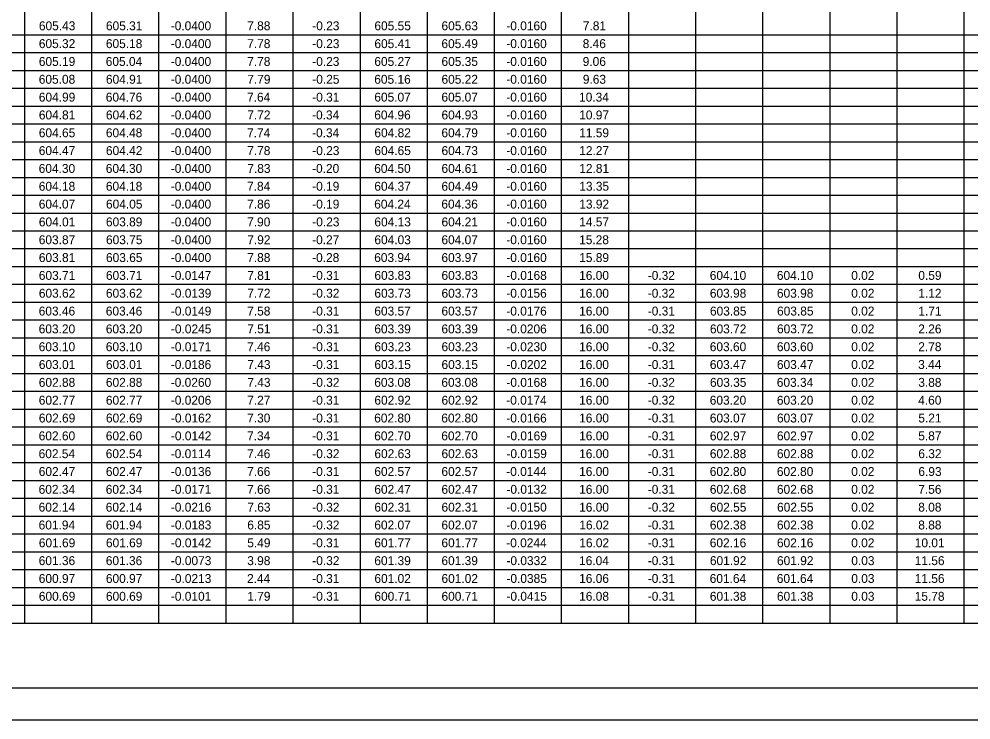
# Model space of a CAD drawing. Extents: x 0 to 34, y 0 to 22.
# Drawn here: x 7.6 to 22.56, y 0 to 11.01 of the extents above; entities that cross this region are included whole.
import ezdxf

# ---------------------------------------------------------------- set-up
doc = ezdxf.new("R2010")
doc.units = 0
for name, color, linetype in [('Default', 7, 'Continuous'), ('SH_Border', 7, 'Continuous'), ('SH_Cut_Line', 7, 'Continuous')]:
    doc.layers.add(name, color=color, linetype=linetype)

msp = doc.modelspace()

# ---------------------------------------------------------------- linework, layer by layer
at = {"layer": 'Default'}
for p, q in [((17.176, 19.376), (17.176, 1.522)), ((22.447, 19.376), (22.447, 1.522)), ((11.906, 18.833), (11.906, 1.522)), ((7.689, 18.52), (7.689, 1.522)), ((8.743, 18.52), (8.743, 1.522)), ((9.797, 18.52), (9.797, 1.522)), ((10.851, 18.52), (10.851, 1.522)), ((12.96, 18.52), (12.96, 1.522)), ((14.014, 18.52), (14.014, 1.522)), ((15.068, 18.52), (15.068, 1.522)), ((16.122, 18.52), (16.122, 1.522)), ((18.23, 18.52), (18.23, 1.522)), ((19.284, 18.52), (19.284, 1.522)), ((20.339, 18.52), (20.339, 1.522)), ((21.393, 18.52), (21.393, 1.522)), ((6.635, 10.762), (26.861, 10.762)), ((6.635, 10.482), (26.861, 10.482)), ((6.635, 10.202), (26.861, 10.202)), ((6.635, 9.922), (26.861, 9.922)), ((6.635, 9.642), (26.861, 9.642)), ((6.635, 9.362), (26.861, 9.362)), ((6.635, 9.082), (26.861, 9.082)), ((6.635, 8.802), (26.861, 8.802)), ((6.635, 8.522), (26.861, 8.522)), ((6.635, 8.242), (26.861, 8.242)), ((6.635, 7.962), (26.861, 7.962)), ((6.635, 7.682), (26.861, 7.682)), ((6.635, 7.402), (26.861, 7.402)), ((6.635, 7.122), (26.861, 7.122)), ((6.635, 6.842), (26.861, 6.842)), ((6.635, 6.562), (26.861, 6.562)), ((6.635, 6.282), (26.861, 6.282)), ((6.635, 6.002), (26.861, 6.002)), ((6.635, 5.722), (26.861, 5.722)), ((6.635, 5.442), (26.861, 5.442)), ((6.635, 5.162), (26.861, 5.162)), ((6.635, 4.882), (26.861, 4.882)), ((6.635, 4.602), (26.861, 4.602)), ((6.635, 4.322), (26.861, 4.322)), ((6.635, 4.042), (26.861, 4.042)), ((6.635, 3.762), (26.861, 3.762)), ((6.635, 3.482), (26.861, 3.482)), ((6.635, 3.202), (26.861, 3.202)), ((6.635, 2.922), (26.861, 2.922)), ((6.635, 2.642), (26.861, 2.642)), ((6.635, 2.362), (26.861, 2.362)), ((6.635, 2.082), (26.861, 2.082)), ((6.635, 1.802), (26.861, 1.802)), ((6.635, 1.522), (26.861, 1.522))]:
    msp.add_line(p, q, dxfattribs=at)
at = {"layer": 'SH_Border'}
msp.add_lwpolyline([(1.5, 21.5), (33.5, 21.5), (33.5, 0.5), (1.5, 0.5)], close=True, dxfattribs=at)
at = {"layer": 'SH_Cut_Line'}
msp.add_lwpolyline([(0, 0), (34, 0), (34, 22), (0, 22)], close=True, dxfattribs=at)

# ---------------------------------------------------------------- texts
at = {"layer": 'Default'}
for s, p in [('605.43', (7.916, 10.832)), ('605.31', (8.969, 10.832)), ('-0.0400', (9.987, 10.832)), ('7.88', (11.188, 10.832)), ('-0.23', (12.21, 10.832)), ('605.55', (13.186, 10.832)), ('605.63', (14.24, 10.832)), ('-0.0160', (15.258, 10.832)), ('7.81', (16.46, 10.832)), ('605.32', (7.915, 10.552)), ('605.18', (8.968, 10.552)), ('-0.0400', (9.987, 10.552)), ('7.78', (11.188, 10.552)), ('-0.23', (12.21, 10.552)), ('605.41', (13.186, 10.552)), ('605.49', (14.239, 10.552)), ('-0.0160', (15.258, 10.552)), ('8.46', (16.458, 10.552)), ('605.19', (7.915, 10.272)), ('605.04', (8.966, 10.272)), ('-0.0400', (9.987, 10.272)), ('7.78', (11.188, 10.272)), ('-0.23', (12.21, 10.272)), ('605.27', (13.185, 10.272)), ('605.35', (14.24, 10.272)), ('-0.0160', (15.258, 10.272)), ('9.06', (16.458, 10.272)), ('605.08', (7.914, 9.992)), ('604.91', (8.969, 9.992)), ('-0.0400', (9.987, 9.992)), ('7.79', (11.189, 9.992)), ('-0.25', (12.21, 9.992)), ('605.16', (13.184, 9.992)), ('605.22', (14.24, 9.992)), ('-0.0160', (15.258, 9.992)), ('9.63', (16.46, 9.992)), ('604.99', (7.915, 9.712)), ('604.76', (8.967, 9.712)), ('-0.0400', (9.987, 9.712)), ('7.64', (11.186, 9.712)), ('-0.31', (12.209, 9.712)), ('605.07', (13.185, 9.712)), ('605.07', (14.239, 9.712)), ('-0.0160', (15.258, 9.712)), ('10.34', (16.401, 9.712)), ('604.81', (7.915, 9.432)), ('604.62', (8.969, 9.432)), ('-0.0400', (9.987, 9.432)), ('7.72', (11.189, 9.432)), ('-0.34', (12.207, 9.432)), ('604.96', (13.184, 9.432)), ('604.93', (14.24, 9.432)), ('-0.0160', (15.258, 9.432)), ('10.97', (16.403, 9.432)), ('604.65', (7.915, 9.152)), ('604.48', (8.968, 9.152)), ('-0.0400', (9.987, 9.152)), ('7.74', (11.186, 9.152)), ('-0.34', (12.207, 9.152)), ('604.82', (13.186, 9.152)), ('604.79', (14.239, 9.152)), ('-0.0160', (15.258, 9.152)), ('11.59', (16.403, 9.152)), ('604.47', (7.914, 8.872)), ('604.42', (8.969, 8.872)), ('-0.0400', (9.987, 8.872)), ('7.78', (11.188, 8.872)), ('-0.23', (12.21, 8.872)), ('604.65', (13.186, 8.872)), ('604.73', (14.24, 8.872)), ('-0.0160', (15.258, 8.872)), ('12.27', (16.403, 8.872)), ('604.30', (7.913, 8.592)), ('604.30', (8.967, 8.592)), ('-0.0400', (9.987, 8.592)), ('7.83', (11.19, 8.592)), ('-0.20', (12.207, 8.592)), ('604.50', (13.183, 8.592)), ('604.61', (14.24, 8.592)), ('-0.0160', (15.258, 8.592)), ('12.81', (16.404, 8.592)), ('604.18', (7.914, 8.312)), ('604.18', (8.968, 8.312)), ('-0.0400', (9.987, 8.312)), ('7.84', (11.186, 8.312)), ('-0.19', (12.209, 8.312)), ('604.37', (13.185, 8.312)), ('604.49', (14.239, 8.312)), ('-0.0160', (15.258, 8.312)), ('13.35', (16.404, 8.312)), ('604.07', (7.914, 8.032)), ('604.05', (8.97, 8.032)), ('-0.0400', (9.987, 8.032)), ('7.86', (11.187, 8.032)), ('-0.19', (12.209, 8.032)), ('604.24', (13.183, 8.032)), ('604.36', (14.238, 8.032)), ('-0.0160', (15.258, 8.032)), ('13.92', (16.404, 8.032)), ('604.01', (7.915, 7.752)), ('603.89', (8.969, 7.752)), ('-0.0400', (9.987, 7.752)), ('7.90', (11.187, 7.752)), ('-0.23', (12.21, 7.752)), ('604.13', (13.186, 7.752)), ('604.21', (14.24, 7.752)), ('-0.0160', (15.258, 7.752)), ('14.57', (16.403, 7.752)), ('603.87', (7.914, 7.472)), ('603.75', (8.97, 7.472)), ('-0.0400', (9.987, 7.472)), ('7.92', (11.189, 7.472)), ('-0.27', (12.208, 7.472)), ('604.03', (13.186, 7.472)), ('604.07', (14.239, 7.472)), ('-0.0160', (15.258, 7.472)), ('15.28', (16.402, 7.472)), ('603.81', (7.915, 7.192)), ('603.65', (8.97, 7.192)), ('-0.0400', (9.987, 7.192)), ('7.88', (11.188, 7.192)), ('-0.28', (12.208, 7.192)), ('603.94', (13.183, 7.192)), ('603.97', (14.239, 7.192)), ('-0.0160', (15.258, 7.192)), ('15.89', (16.403, 7.192)), ('603.71', (7.915, 6.912)), ('603.71', (8.969, 6.912)), ('-0.0147', (9.988, 6.912)), ('7.81', (11.189, 6.912)), ('-0.31', (12.209, 6.912)), ('603.83', (13.186, 6.912)), ('603.83', (14.24, 6.912)), ('-0.0168', (15.259, 6.912)), ('16.00', (16.402, 6.912)), ('-0.32', (17.48, 6.912)), ('604.10', (18.454, 6.912)), ('604.10', (19.508, 6.912)), ('0.02', (20.676, 6.912)), ('0.59', (21.73, 6.912)), ('603.62', (7.915, 6.632)), ('603.62', (8.969, 6.632)), ('-0.0139', (9.989, 6.632)), ('7.72', (11.189, 6.632)), ('-0.32', (12.21, 6.632)), ('603.73', (13.186, 6.632)), ('603.73', (14.24, 6.632)), ('-0.0156', (15.258, 6.632)), ('16.00', (16.402, 6.632)), ('-0.32', (17.48, 6.632)), ('603.98', (18.455, 6.632)), ('603.98', (19.509, 6.632)), ('0.02', (20.676, 6.632)), ('1.12', (21.73, 6.632)), ('603.46', (7.913, 6.352)), ('603.46', (8.967, 6.352)), ('-0.0149', (9.989, 6.352)), ('7.58', (11.188, 6.352)), ('-0.31', (12.209, 6.352)), ('603.57', (13.185, 6.352)), ('603.57', (14.239, 6.352)), ('-0.0176', (15.258, 6.352)), ('16.00', (16.402, 6.352)), ('-0.31', (17.48, 6.352)), ('603.85', (18.457, 6.352)), ('603.85', (19.511, 6.352)), ('0.02', (20.676, 6.352)), ('1.71', (21.73, 6.352)), ('603.20', (7.913, 6.072)), ('603.20', (8.967, 6.072)), ('-0.0245', (9.99, 6.072)), ('7.51', (11.189, 6.072)), ('-0.31', (12.209, 6.072)), ('603.39', (13.185, 6.072)), ('603.39', (14.239, 6.072)), ('-0.0206', (15.258, 6.072)), ('16.00', (16.402, 6.072)), ('-0.32', (17.48, 6.072)), ('603.72', (18.456, 6.072)), ('603.72', (19.51, 6.072)), ('0.02', (20.676, 6.072)), ('2.26', (21.729, 6.072)), ('603.10', (7.913, 5.792)), ('603.10', (8.967, 5.792)), ('-0.0171', (9.989, 5.792)), ('7.46', (11.187, 5.792)), ('-0.31', (12.209, 5.792)), ('603.23', (13.186, 5.792)), ('603.23', (14.24, 5.792)), ('-0.0230', (15.258, 5.792)), ('16.00', (16.402, 5.792)), ('-0.32', (17.48, 5.792)), ('603.60', (18.454, 5.792)), ('603.60', (19.508, 5.792)), ('0.02', (20.676, 5.792)), ('2.78', (21.729, 5.792)), ('603.01', (7.915, 5.512)), ('603.01', (8.969, 5.512)), ('-0.0186', (9.988, 5.512)), ('7.43', (11.19, 5.512)), ('-0.31', (12.209, 5.512)), ('603.15', (13.186, 5.512)), ('603.15', (14.24, 5.512)), ('-0.0202', (15.26, 5.512)), ('16.00', (16.402, 5.512)), ('-0.31', (17.48, 5.512)), ('603.47', (18.455, 5.512)), ('603.47', (19.509, 5.512)), ('0.02', (20.676, 5.512)), ('3.44', (21.727, 5.512)), ('602.88', (7.914, 5.232)), ('602.88', (8.968, 5.232)), ('-0.0260', (9.987, 5.232)), ('7.43', (11.19, 5.232)), ('-0.32', (12.21, 5.232)), ('603.08', (13.184, 5.232)), ('603.08', (14.238, 5.232)), ('-0.0168', (15.259, 5.232)), ('16.00', (16.402, 5.232)), ('-0.32', (17.48, 5.232)), ('603.35', (18.457, 5.232)), ('603.34', (19.507, 5.232)), ('0.02', (20.676, 5.232)), ('3.88', (21.729, 5.232)), ('602.77', (7.914, 4.952)), ('602.77', (8.968, 4.952)), ('-0.0206', (9.988, 4.952)), ('7.27', (11.188, 4.952)), ('-0.31', (12.209, 4.952)), ('602.92', (13.186, 4.952)), ('602.92', (14.24, 4.952)), ('-0.0174', (15.257, 4.952)), ('16.00', (16.402, 4.952)), ('-0.32', (17.48, 4.952)), ('603.20', (18.454, 4.952)), ('603.20', (19.508, 4.952)), ('0.02', (20.676, 4.952)), ('4.60', (21.728, 4.952)), ('602.69', (7.915, 4.672)), ('602.69', (8.969, 4.672)), ('-0.0162', (9.99, 4.672)), ('7.30', (11.187, 4.672)), ('-0.31', (12.209, 4.672)), ('602.80', (13.183, 4.672)), ('602.80', (14.237, 4.672)), ('-0.0166', (15.258, 4.672)), ('16.00', (16.402, 4.672)), ('-0.31', (17.48, 4.672)), ('603.07', (18.455, 4.672)), ('603.07', (19.509, 4.672)), ('0.02', (20.676, 4.672)), ('5.21', (21.73, 4.672)), ('602.60', (7.913, 4.392)), ('602.60', (8.967, 4.392)), ('-0.0142', (9.99, 4.392)), ('7.34', (11.186, 4.392)), ('-0.31', (12.209, 4.392)), ('602.70', (13.183, 4.392)), ('602.70', (14.237, 4.392)), ('-0.0169', (15.26, 4.392)), ('16.00', (16.402, 4.392)), ('-0.31', (17.48, 4.392)), ('602.97', (18.455, 4.392)), ('602.97', (19.509, 4.392)), ('0.02', (20.676, 4.392)), ('5.87', (21.729, 4.392)), ('602.54', (7.912, 4.112)), ('602.54', (8.966, 4.112)), ('-0.0114', (9.987, 4.112)), ('7.46', (11.187, 4.112)), ('-0.32', (12.21, 4.112)), ('602.63', (13.186, 4.112)), ('602.63', (14.24, 4.112)), ('-0.0159', (15.26, 4.112)), ('16.00', (16.402, 4.112)), ('-0.31', (17.48, 4.112)), ('602.88', (18.455, 4.112)), ('602.88', (19.509, 4.112)), ('0.02', (20.676, 4.112)), ('6.32', (21.73, 4.112)), ('602.47', (7.914, 3.832)), ('602.47', (8.968, 3.832)), ('-0.0136', (9.988, 3.832)), ('7.66', (11.187, 3.832)), ('-0.31', (12.209, 3.832)), ('602.57', (13.185, 3.832)), ('602.57', (14.239, 3.832)), ('-0.0144', (15.257, 3.832)), ('16.00', (16.402, 3.832)), ('-0.31', (17.48, 3.832)), ('602.80', (18.454, 3.832)), ('602.80', (19.508, 3.832)), ('0.02', (20.676, 3.832)), ('6.93', (21.731, 3.832)), ('602.34', (7.912, 3.552)), ('602.34', (8.966, 3.552)), ('-0.0171', (9.989, 3.552)), ('7.66', (11.187, 3.552)), ('-0.31', (12.209, 3.552)), ('602.47', (13.185, 3.552)), ('602.47', (14.239, 3.552)), ('-0.0132', (15.26, 3.552)), ('16.00', (16.402, 3.552)), ('-0.31', (17.48, 3.552)), ('602.68', (18.455, 3.552)), ('602.68', (19.509, 3.552)), ('0.02', (20.676, 3.552)), ('7.56', (21.729, 3.552)), ('602.14', (7.912, 3.272)), ('602.14', (8.966, 3.272)), ('-0.0216', (9.988, 3.272)), ('7.63', (11.19, 3.272)), ('-0.32', (12.21, 3.272)), ('602.31', (13.186, 3.272)), ('602.31', (14.24, 3.272)), ('-0.0150', (15.258, 3.272)), ('16.00', (16.402, 3.272)), ('-0.32', (17.48, 3.272)), ('602.55', (18.457, 3.272)), ('602.55', (19.511, 3.272)), ('0.02', (20.676, 3.272)), ('8.08', (21.729, 3.272)), ('601.94', (7.912, 2.992)), ('601.94', (8.966, 2.992)), ('-0.0183', (9.99, 2.992)), ('6.85', (11.189, 2.992)), ('-0.32', (12.21, 2.992)), ('602.07', (13.185, 2.992)), ('602.07', (14.239, 2.992)), ('-0.0196', (15.258, 2.992)), ('16.02', (16.404, 2.992)), ('-0.31', (17.48, 2.992)), ('602.38', (18.455, 2.992)), ('602.38', (19.509, 2.992)), ('0.02', (20.676, 2.992)), ('8.88', (21.729, 2.992)), ('601.69', (7.915, 2.712)), ('601.69', (8.969, 2.712)), ('-0.0142', (9.99, 2.712)), ('5.49', (11.189, 2.712)), ('-0.31', (12.209, 2.712)), ('601.77', (13.185, 2.712)), ('601.77', (14.239, 2.712)), ('-0.0244', (15.257, 2.712)), ('16.02', (16.404, 2.712)), ('-0.31', (17.48, 2.712)), ('602.16', (18.454, 2.712)), ('602.16', (19.509, 2.712)), ('0.02', (20.676, 2.712)), ('10.01', (21.674, 2.712)), ('601.36', (7.913, 2.432)), ('601.36', (8.967, 2.432)), ('-0.0073', (9.99, 2.432)), ('3.98', (11.188, 2.432)), ('-0.32', (12.21, 2.432)), ('601.39', (13.185, 2.432)), ('601.39', (14.239, 2.432)), ('-0.0332', (15.26, 2.432)), ('16.04', (16.401, 2.432)), ('-0.31', (17.48, 2.432)), ('601.92', (18.456, 2.432)), ('601.92', (19.51, 2.432)), ('0.03', (20.677, 2.432)), ('11.56', (21.673, 2.432)), ('600.97', (7.914, 2.152)), ('600.97', (8.968, 2.152)), ('-0.0213', (9.99, 2.152)), ('2.44', (11.186, 2.152)), ('-0.31', (12.209, 2.152)), ('601.02', (13.186, 2.152)), ('601.02', (14.24, 2.152)), ('-0.0385', (15.26, 2.152)), ('16.06', (16.402, 2.152)), ('-0.31', (17.48, 2.152)), ('601.64', (18.453, 2.152)), ('601.64', (19.507, 2.152)), ('0.03', (20.677, 2.152)), ('11.56', (21.673, 2.152)), ('600.69', (7.915, 1.872)), ('600.69', (8.969, 1.872)), ('-0.0101', (9.989, 1.872)), ('1.79', (11.189, 1.872)), ('-0.31', (12.209, 1.872)), ('600.71', (13.186, 1.872)), ('600.71', (14.24, 1.872)), ('-0.0415', (15.26, 1.872)), ('16.08', (16.402, 1.872)), ('-0.31', (17.48, 1.872)), ('601.38', (18.455, 1.872)), ('601.38', (19.509, 1.872)), ('0.03', (20.677, 1.872)), ('15.78', (21.673, 1.872))]:
    msp.add_text(s, height=0.14, dxfattribs=at).set_placement(p)

doc.saveas('drawing.dxf')
